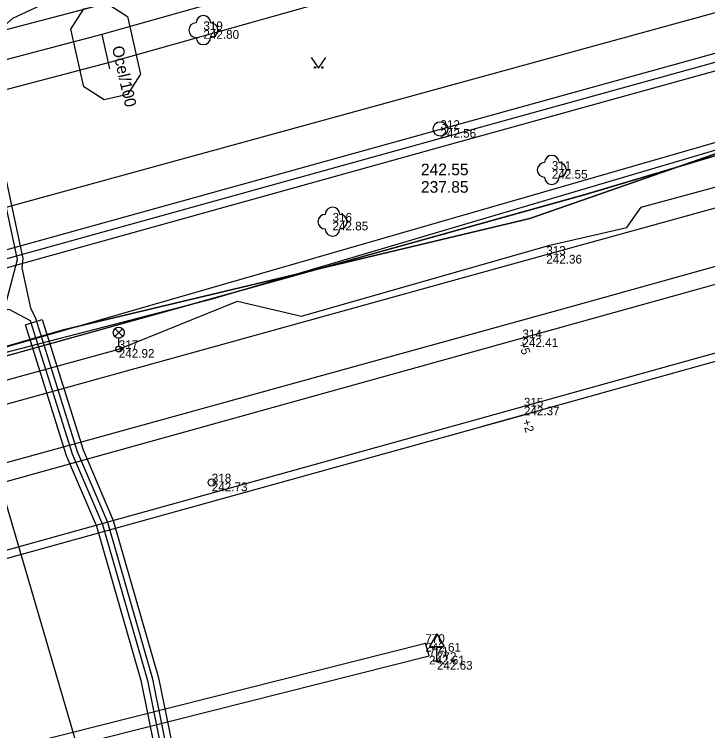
# Model space of a CAD drawing. Extents: x -599432 to -598680, y -1159407 to -1158632.
# Drawn here: x -599106.02 to -599082.18, y -1158925.7 to -1158901.06 of the extents above; entities that cross this region are included whole.
import ezdxf

# ---------------------------------------------------------------- set-up
doc = ezdxf.new("R2010")
doc.units = 0
for name, color, linetype in [('0004 VY - Body podrobné', 7, 'Continuous'), ('0005 VY - Body podrobné - čísla', 7, 'Continuous'), ('0006 VY - Body podrobné - výšky', 7, 'Continuous'), ('0024 ZA - Podezdívka', 7, 'Continuous'), ('0027 ZA - Silnice_cesta zpevněná', 7, 'Continuous'), ('0028 ZA - Silnice - nájezd na chodník', 7, 'Continuous'), ('0030 ZA - Chodník', 7, 'Continuous'), ('0031 ZA - Ostatní rozhraní', 7, 'Continuous'), ('0034 ZA - Kultury - značky', 7, 'Continuous'), ('0035 ZA - Strom - značka', 7, 'Continuous'), ('0062 ZA - Doprava - dopravní značky', 7, 'Continuous'), ('0073 TE - Výška obrubníků a zdí', 7, 'Continuous'), ('0075 ZA - BVK - kanalizace - buňky', 7, 'Continuous'), ('0092 ZA - RWE - plynovod - buňky', 7, 'Continuous'), ('0105 ZA - TSB - VO - buňky', 7, 'Continuous'), ('0201 PV - BVK - kanalizace - popis', 7, 'Continuous'), ('0202 PV - MUNI', 7, 'Continuous'), ('0206 PV - BVK - kanalizace - jednotná', 7, 'Continuous'), ('0211 PV - BVK - kanalizace - jednotná okraj', 7, 'Continuous'), ('0264 PV - TB - parovod mimo provoz', 7, 'Continuous'), ('0301 PV - RWE - popis', 7, 'Continuous'), ('0302 PV - RWE - NTL', 7, 'Continuous'), ('0308 PV - RWE - ochranné pásmo', 7, 'Continuous'), ('0354 PV - EON - VN', 7, 'Continuous'), ('0359 PV - EON - sdělovací kabely', 7, 'Continuous'), ('0367 PV - EON - VN chránička', 7, 'Continuous'), ('0407 PV - TSB - kabelové vedení přibližný zákres', 7, 'Continuous'), ('0454 PV - O2 - kabel zaměřený', 7, 'Continuous'), ('0530 PV - T-mobile - optické kabely', 7, 'Continuous'), ('0652 PV - BKOM - kabely bez rozlišení', 7, 'Continuous'), ('0703 PV - DIAL TELECOM optický kabel', 7, 'Continuous'), ('0704 PV - ČD - kabely', 7, 'Continuous')]:
    doc.layers.add(name, color=color, linetype=linetype)

msp = doc.modelspace()

# ---------------------------------------------------------------- linework, layer by layer
at = {"layer": '0004 VY - Body podrobné'}
for p, q in [((-599099.52, -1158901.6), (-599099.52, -1158901.6)), ((-599091.37, -1158905), (-599091.37, -1158905)), ((-599087.54, -1158906.41), (-599087.54, -1158906.41)), ((-599095.08, -1158908.19), (-599095.08, -1158908.19)), ((-599087.73, -1158909.33), (-599087.73, -1158909.33)), ((-599088.55, -1158912.2), (-599088.55, -1158912.2)), ((-599102.43, -1158912.57), (-599102.43, -1158912.57)), ((-599088.5, -1158914.55), (-599088.5, -1158914.55)), ((-599099.23, -1158917.16), (-599099.23, -1158917.16)), ((-599091.89, -1158922.68), (-599091.89, -1158922.68)), ((-599091.76, -1158923.12), (-599091.76, -1158923.12)), ((-599091.49, -1158923.3), (-599091.49, -1158923.3))]:
    msp.add_line(p, q, dxfattribs=at)
at = {"layer": '0024 ZA - Podezdívka'}
for p, q in [((-599105.558, -1158926.136), (-599091.888, -1158922.688)), ((-599091.76, -1158923.12), (-599091.888, -1158922.688)), ((-599105.44, -1158926.57), (-599091.76, -1158923.12))]:
    msp.add_line(p, q, dxfattribs=at)
at = {"layer": '0027 ZA - Silnice_cesta zpevněná'}
for p, q in [((-599061.79, -1158904.74), (-599088.55, -1158912.2)), ((-599088.55, -1158912.2), (-599137.26, -1158925.73))]:
    msp.add_line(p, q, dxfattribs=at)
at = {"layer": '0028 ZA - Silnice - nájezd na chodník'}
for p, q in [((-599060.19, -1158906.64), (-599088.5, -1158914.55)), ((-599088.5, -1158914.55), (-599147.65, -1158930.98))]:
    msp.add_line(p, q, dxfattribs=at)
at = {"layer": '0030 ZA - Chodník'}
for p, q in [((-599063.78, -1158902.71), (-599087.73, -1158909.33)), ((-599087.73, -1158909.33), (-599109.02, -1158915.23))]:
    msp.add_line(p, q, dxfattribs=at)
at = {"layer": '0031 ZA - Ostatní rozhraní'}
for p, q in [((-599062.365, -1158907.539), (-599089.968, -1158915.251)), ((-599088.425, -1158914.82), (-599146.72, -1158931.012))]:
    msp.add_line(p, q, dxfattribs=at)
at = {"layer": '0034 ZA - Kultury - značky'}
msp.add_lwpolyline([(-599095.809, -1158902.537), (-599095.559, -1158902.912), (-599095.309, -1158902.537)], dxfattribs=at)
for centre in [(-599095.684, -1158902.887), (-599095.434, -1158902.887)]:
    msp.add_circle(centre, 0.025, dxfattribs=at)
at = {"layer": '0035 ZA - Strom - značka'}
for centre in [(-599099.52, -1158901.6), (-599087.54, -1158906.41), (-599095.08, -1158908.19)]:
    msp.add_circle(centre, 0.00025, dxfattribs=at)
for centre, start, end in [((-599099.52, -1158901.35), 0, 180), ((-599099.77, -1158901.6), 90, 270), ((-599099.27, -1158901.6), 270, 90), ((-599099.52, -1158901.85), 180, 360), ((-599087.54, -1158906.16), 0, 180), ((-599087.79, -1158906.41), 90, 270), ((-599087.29, -1158906.41), 270, 90), ((-599087.54, -1158906.66), 180, 360), ((-599095.08, -1158907.94), 0, 180), ((-599095.33, -1158908.19), 90, 270), ((-599094.83, -1158908.19), 270, 90), ((-599095.08, -1158908.44), 180, 360)]:
    msp.add_arc(centre, 0.25, start, end, dxfattribs=at)
at = {"layer": '0062 ZA - Doprava - dopravní značky'}
for p, q in [((-599091.49, -1158922.367), (-599091.74, -1158922.8)), ((-599091.49, -1158922.367), (-599091.24, -1158922.8)), ((-599091.74, -1158922.8), (-599091.24, -1158922.8)), ((-599091.49, -1158923.3), (-599091.49, -1158922.8)), ((-599091.615, -1158923.3), (-599091.365, -1158923.3))]:
    msp.add_line(p, q, dxfattribs=at)
at = {"layer": '0075 ZA - BVK - kanalizace - buňky'}
msp.add_circle((-599091.37, -1158905), 0.25, dxfattribs=at)
at = {"layer": '0092 ZA - RWE - plynovod - buňky'}
msp.add_circle((-599099.23, -1158917.16), 0.125, dxfattribs=at)
at = {"layer": '0105 ZA - TSB - VO - buňky'}
for p, q in [((-599102.562, -1158912.139), (-599102.298, -1158911.875)), ((-599102.294, -1158912.138), (-599102.558, -1158911.873)), ((-599102.43, -1158912.47), (-599102.43, -1158912.195))]:
    msp.add_line(p, q, dxfattribs=at)
for centre, radius in [((-599102.43, -1158912.008), 0.188), ((-599102.43, -1158912.57), 0.1)]:
    msp.add_circle(centre, radius, dxfattribs=at)
at = {"layer": '0202 PV - MUNI'}
msp.add_lwpolyline([(-599146.637, -1158922.988), (-599125.848, -1158917.745), (-599099.176, -1158910.829), (-599079.1, -1158904.889), (-599063.715, -1158899.846), (-599061.634, -1158898.405), (-599061.066, -1158896.468), (-599061.778, -1158890.969), (-599061.202, -1158889.928), (-599056.191, -1158887.591), (-599053.917, -1158887.479), (-599048.522, -1158885.349), (-599047.385, -1158884.453), (-599040.021, -1158881.203), (-599032.673, -1158878.601), (-599020.545, -1158875.063), (-599018.496, -1158874.767), (-599015.655, -1158876.808), (-599014.942, -1158877.801)], dxfattribs=at)
at = {"layer": '0206 PV - BVK - kanalizace - jednotná'}
for p, q in [((-599091.321, -1158905.303), (-599035.766, -1158889.94)), ((-599158.607, -1158924.017), (-599091.321, -1158905.303))]:
    msp.add_line(p, q, dxfattribs=at)
at = {"layer": '0211 PV - BVK - kanalizace - jednotná okraj'}
for p, q in [((-599091.401, -1158905.014), (-599035.846, -1158889.651)), ((-599035.686, -1158890.229), (-599091.242, -1158905.592)), ((-599158.687, -1158923.728), (-599091.402, -1158905.014)), ((-599091.241, -1158905.592), (-599158.526, -1158924.307))]:
    msp.add_line(p, q, dxfattribs=at)
at = {"layer": '0264 PV - TB - parovod mimo provoz'}
msp.add_line((-599074.078, -1158898.846), (-599160.39, -1158922.56), dxfattribs=at)
at = {"layer": '0302 PV - RWE - NTL'}
for points in [[(-599042.76, -1158885.49), (-599068.42, -1158892.17), (-599094.54, -1158899.36), (-599103.01, -1158901.75), (-599109.28, -1158903.4), (-599121.29, -1158906.57), (-599128.03, -1158908.44), (-599139.52, -1158911.687), (-599140.38, -1158911.93), (-599166.16, -1158919.18), (-599194.33, -1158927.1), (-599199.24, -1158928.46), (-599225.65, -1158935.9)], [(-599103.01, -1158901.75), (-599102.746, -1158902.931)]]:
    msp.add_lwpolyline(points, dxfattribs=at)
at = {"layer": '0308 PV - RWE - ochranné pásmo'}
for points in [[(-599166.431, -1158918.217), (-599140.651, -1158910.968), (-599139.792, -1158910.725), (-599128.3, -1158907.477), (-599121.551, -1158905.605), (-599109.535, -1158902.433), (-599103.273, -1158900.785), (-599094.808, -1158898.397), (-599068.679, -1158891.204), (-599043.012, -1158884.522)], [(-599042.508, -1158886.458), (-599068.161, -1158893.136), (-599094.272, -1158900.323), (-599102.747, -1158902.715), (-599109.025, -1158904.367), (-599121.029, -1158907.535), (-599127.76, -1158909.403), (-599139.248, -1158912.649), (-599140.109, -1158912.892), (-599165.889, -1158920.143)]]:
    msp.add_lwpolyline(points, dxfattribs=at)
msp.add_lwpolyline([(-599102.124, -1158901.128), (-599102.034, -1158901.532), (-599101.77, -1158902.713), (-599101.68, -1158903.117), (-599102.124, -1158903.817), (-599102.528, -1158903.907), (-599102.932, -1158903.997), (-599103.632, -1158903.553), (-599103.722, -1158903.149), (-599103.986, -1158901.968), (-599104.076, -1158901.564), (-599103.632, -1158900.864), (-599103.228, -1158900.774), (-599102.824, -1158900.684)], close=True, dxfattribs=at)
at = {"layer": '0354 PV - EON - VN'}
for points in [[(-599100.02, -1158930.068), (-599101.253, -1158923.926), (-599102.806, -1158918.536), (-599103.846, -1158916.105), (-599105.285, -1158911.524), (-599105.454, -1158911.165), (-599105.752, -1158909.781), (-599105.72, -1158909.453), (-599106.602, -1158905.369), (-599106.913, -1158903.886), (-599107.107, -1158903.206), (-599106.839, -1158901.863), (-599106.075, -1158901.185), (-599105.137, -1158900.755), (-599099.225, -1158899.297), (-599095.622, -1158898.316), (-599094.203, -1158897.866), (-599092.546, -1158897.477), (-599083.302, -1158895.086), (-599074.947, -1158892.385), (-599069.734, -1158890.453), (-599068.354, -1158889.893), (-599062.365, -1158887.674)], [(-599106.311, -1158911.019), (-599105.916, -1158909.495), (-599106.798, -1158905.411)], [(-599145.481, -1158921.466), (-599140.483, -1158919.816), (-599136.355, -1158918.837), (-599130.655, -1158917.267), (-599126.136, -1158916.177), (-599122.299, -1158915.198), (-599120.36, -1158914.878), (-599115.595, -1158913.737), (-599111.233, -1158912.526), (-599109.544, -1158912.057), (-599106.208, -1158911.199), (-599105.476, -1158911.584), (-599104.034, -1158916.175), (-599102.994, -1158918.604), (-599101.447, -1158923.974), (-599100.22, -1158930.092), (-599099.87, -1158938.117), (-599099.769, -1158939.21), (-599099.658, -1158940.222)]]:
    msp.add_lwpolyline(points, dxfattribs=at)
at = {"layer": '0359 PV - EON - sdělovací kabely'}
msp.add_lwpolyline([(-599153, -1158925.67), (-599136.91, -1158920.86), (-599119.51, -1158916.31), (-599104.33, -1158911.91), (-599088.3, -1158908.08), (-599074.72, -1158903.34), (-599063.86, -1158900.66), (-599061.95, -1158898.88), (-599061.24, -1158895.32), (-599061.55, -1158893.87), (-599062.09, -1158890.79), (-599061.3, -1158889.79), (-599054.31, -1158887.73), (-599051.84, -1158888.39), (-598992.76, -1158891.74), (-598991.64, -1158891.24), (-598990.73, -1158890.27)], dxfattribs=at)
msp.add_lwpolyline([(-599153, -1158925.67), (-599136.91, -1158920.86), (-599119.51, -1158916.31), (-599104.33, -1158911.91), (-599088.3, -1158908.08), (-599074.72, -1158903.34), (-599063.86, -1158900.66), (-599061.95, -1158898.88), (-599061.24, -1158895.32), (-599061.55, -1158893.87), (-599062.09, -1158890.79), (-599061.3, -1158889.79), (-599054.31, -1158887.73), (-599051.84, -1158888.39), (-598992.76, -1158891.74), (-598991.64, -1158891.24), (-598990.73, -1158890.27)], dxfattribs=at)
at = {"layer": '0367 PV - EON - VN chránička'}
for p, q in [((-599105.636, -1158911.74), (-599105.064, -1158911.56)), ((-599105.064, -1158911.56), (-599103.658, -1158916.036)), ((-599104.222, -1158916.244), (-599105.636, -1158911.74)), ((-599103.183, -1158918.671), (-599104.222, -1158916.244)), ((-599103.658, -1158916.036), (-599102.617, -1158918.469)), ((-599102.617, -1158918.469), (-599101.058, -1158923.879)), ((-599101.642, -1158924.021), (-599103.183, -1158918.671)), ((-599101.058, -1158923.879), (-599099.821, -1158930.044)), ((-599100.419, -1158930.116), (-599101.642, -1158924.021))]:
    msp.add_line(p, q, dxfattribs=at)
at = {"layer": '0407 PV - TSB - kabelové vedení přibližný zákres'}
for p, q in [((-599084.471, -1158907.686), (-599074.832, -1158905.09)), ((-599084.956, -1158908.394), (-599084.471, -1158907.686)), ((-599087.603, -1158908.994), (-599084.956, -1158908.394)), ((-599096.152, -1158911.444), (-599087.603, -1158908.994)), ((-599102.43, -1158912.57), (-599098.346, -1158910.92)), ((-599098.346, -1158910.92), (-599096.152, -1158911.444)), ((-599111.96, -1158915.201), (-599102.43, -1158912.57))]:
    msp.add_line(p, q, dxfattribs=at)
at = {"layer": '0454 PV - O2 - kabel zaměřený'}
msp.add_lwpolyline([(-599146.63, -1158923.2), (-599137.96, -1158921.08), (-599126, -1158917.94), (-599115.1, -1158915.26), (-599086.38, -1158907.25), (-599065.99, -1158901.17), (-599063.3, -1158900.18)], dxfattribs=at)
at = {"layer": '0530 PV - T-mobile - optické kabely'}
for points in [[(-599086.381, -1158907.243), (-599065.986, -1158901.164)], [(-599088.299, -1158908.079), (-599074.72, -1158903.34)], [(-599115.101, -1158915.255), (-599086.381, -1158907.243)], [(-599104.33, -1158911.91), (-599088.299, -1158908.079)], [(-599119.509, -1158916.309), (-599104.33, -1158911.91)]]:
    msp.add_lwpolyline(points, dxfattribs=at)
at = {"layer": '0652 PV - BKOM - kabely bez rozlišení'}
msp.add_lwpolyline([(-599152.64, -1158929.37), (-599137, -1158924.99), (-599119.82, -1158920.2), (-599103.66, -1158915.75), (-599086.95, -1158911.13), (-599069.54, -1158906.27), (-599056.01, -1158902.46)], dxfattribs=at)
at = {"layer": '0703 PV - DIAL TELECOM optický kabel'}
msp.add_line((-599107.768, -1158912.907), (-599098.65, -1158944.06), dxfattribs=at)
msp.add_lwpolyline([(-599061.55, -1158893.87), (-599061.24, -1158895.32), (-599061.95, -1158898.88), (-599063.86, -1158900.66), (-599074.72, -1158903.34), (-599088.3, -1158908.08), (-599104.33, -1158911.91), (-599119.51, -1158916.31), (-599136.91, -1158920.86), (-599153, -1158925.67), (-599169.02, -1158930.6), (-599175.84, -1158932.87), (-599181.15, -1158933.71), (-599192.69, -1158937.18), (-599194.75, -1158937.1), (-599197.14, -1158935.93), (-599198.47, -1158933.96), (-599200.36, -1158929.03), (-599200.83, -1158928.66), (-599207.11, -1158930.84)], dxfattribs=at)
at = {"layer": '0704 PV - ČD - kabely'}
msp.add_lwpolyline([(-599063.507, -1158900.144), (-599114.022, -1158914.733), (-599146.63, -1158923.02)], dxfattribs=at)

# ---------------------------------------------------------------- texts
at = {"layer": '0005 VY - Body podrobné - čísla'}
for s, p in [('319', (-599099.52, -1158901.6)), ('312', (-599091.37, -1158905)), ('311', (-599087.54, -1158906.41)), ('316', (-599095.08, -1158908.19)), ('313', (-599087.73, -1158909.33)), ('314', (-599088.55, -1158912.2)), ('317', (-599102.43, -1158912.57)), ('315', (-599088.5, -1158914.55)), ('318', (-599099.23, -1158917.16)), ('770', (-599091.89, -1158922.68)), ('771', (-599091.76, -1158923.12)), ('772', (-599091.49, -1158923.3))]:
    msp.add_text(s, height=0.3, dxfattribs=at).set_placement(p)
at = {"layer": '0006 VY - Body podrobné - výšky'}
for s, p in [('242.80', (-599099.52, -1158901.9)), ('242.56', (-599091.37, -1158905.3)), ('242.55', (-599087.54, -1158906.71)), ('242.85', (-599095.08, -1158908.49)), ('242.36', (-599087.73, -1158909.63)), ('242.41', (-599088.55, -1158912.5)), ('242.92', (-599102.43, -1158912.87)), ('242.37', (-599088.5, -1158914.85)), ('242.73', (-599099.23, -1158917.46)), ('242.61', (-599091.89, -1158922.98)), ('242.61', (-599091.76, -1158923.42)), ('242.63', (-599091.49, -1158923.6))]:
    msp.add_text(s, height=0.3, dxfattribs=at).set_placement(p)
at = {"layer": '0073 TE - Výška obrubníků a zdí'}
for s, p in [('+5', (-599088.688, -1158912.357)), ('+2', (-599088.562, -1158915.034))]:
    msp.add_text(s, height=0.3, rotation=286.775, dxfattribs=at).set_placement(p)
at = {"layer": '0201 PV - BVK - kanalizace - popis'}
for s, p in [('242.55', (-599092.039, -1158906.594)), ('237.85', (-599092.039, -1158907.194))]:
    msp.add_text(s, height=0.4, dxfattribs=at).set_placement(p)
at = {"layer": '0301 PV - RWE - popis'}
msp.add_text('Ocel/100', height=0.4, rotation=282.6007, dxfattribs=at).set_placement((-599102.667, -1158902.189))

doc.saveas('drawing.dxf')
